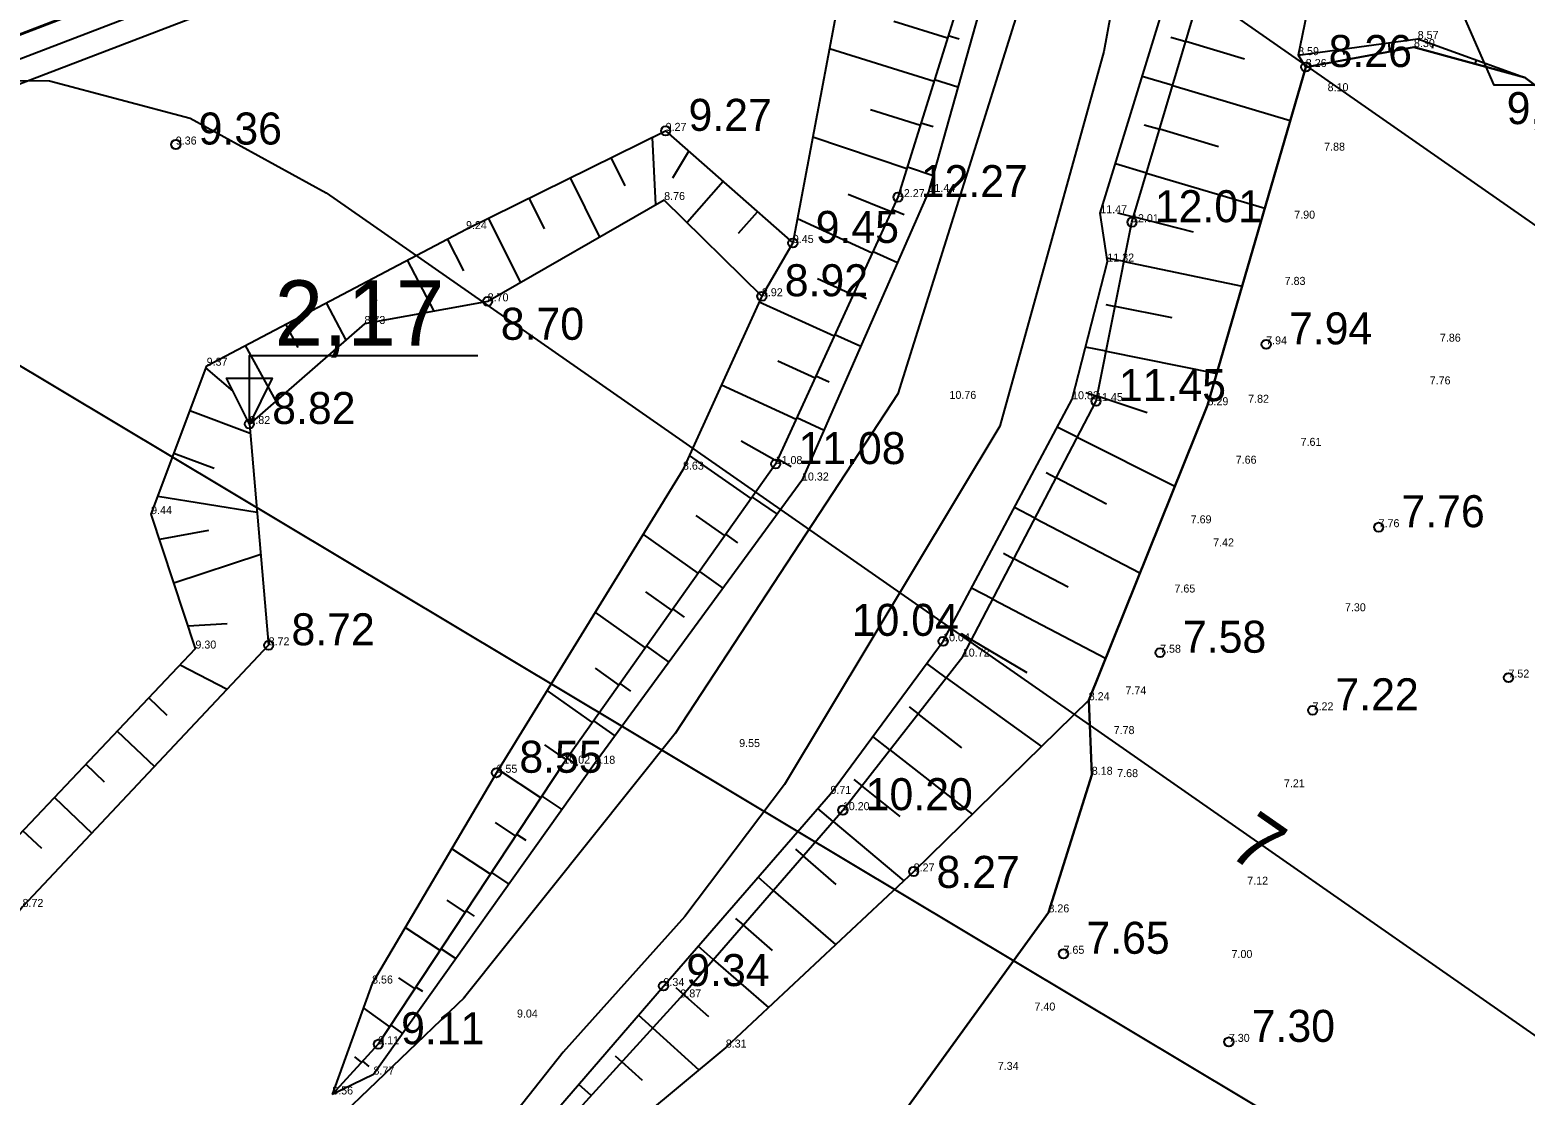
# Model space of a CAD drawing. Extents: x 433497 to 434382, y 6534486 to 6534993.
# Drawn here: x 433879.3 to 433944.7, y 6534844.8 to 6534891.4 of the extents above; entities that cross this region are included whole.
import ezdxf

# ---------------------------------------------------------------- set-up
doc = ezdxf.new("R2010")
doc.units = 0
for name, color, linetype in [('Default', 7, 'Continuous'), ('jääkpaksus', 7, 'Continuous'), ('kataster', 7, 'Continuous'), ('KORGUS-EH2000', 7, 'Continuous'), ('l__x00e4__bil__x00f5__iked', 7, 'Continuous'), ('Lamami horisontaal', 7, 'Continuous'), ('MOOTKORG-EH2000', 7, 'Continuous'), ('PIIR', 7, 'Continuous'), ('RELJEEF', 7, 'Continuous'), ('TEE', 7, 'Continuous'), ('TRUUP', 7, 'Continuous'), ('VEEKOGU', 7, 'Continuous')]:
    doc.layers.add(name, color=color, linetype=linetype)

msp = doc.modelspace()

# ---------------------------------------------------------------- linework, layer by layer
at = {"layer": 'Default'}
msp.add_lwpolyline([(433617.12, 6534791.025), (433632.75, 6534606.045), (434137.38, 6534796.515), (434127.69, 6534855.6), (433968.21, 6534911.925), (433942.38, 6534904.035), (433920.99, 6534907.275)], close=True, dxfattribs=at)
msp.add_lwpolyline([(433617.12, 6534791.025), (433632.75, 6534606.045), (434137.38, 6534796.515), (434127.69, 6534855.6), (433968.21, 6534911.925), (433942.38, 6534904.035), (433920.99, 6534907.275)], close=True, dxfattribs=at)
msp.add_lwpolyline([(433617.12, 6534791.025), (433632.75, 6534606.045), (434137.38, 6534796.515), (434127.69, 6534855.6), (433968.21, 6534911.925), (433942.38, 6534904.035), (433920.99, 6534907.275)], close=True, dxfattribs=at)
at = {"layer": 'jääkpaksus'}
msp.add_lwpolyline([(433888.875, 6534874.127), (433888.875, 6534877.127), (433898.875, 6534877.127)], dxfattribs=at)
msp.add_lwpolyline([(433888.875, 6534874.127), (433887.875, 6534876.127), (433889.875, 6534876.127)], close=True, dxfattribs=at)
at = {"layer": 'kataster'}
msp.add_lwpolyline([(433617.102, 6534791.002), (433632.769, 6534606.029), (434137.446, 6534796.469), (434127.827, 6534855.589), (433950.026, 6534918.39)], close=True, dxfattribs=at)
at = {"layer": 'KORGUS-EH2000'}
for centre in [(433935.088, 6534889.742), (433907.086, 6534886.949), (433885.657, 6534886.351), (433917.246, 6534884.05), (433927.486, 6534882.954), (433912.65, 6534882.047), (433899.301, 6534879.492), (433911.296, 6534879.715), (433933.355, 6534877.61), (433925.913, 6534875.128), (433888.875, 6534874.127), (433911.896, 6534872.374), (433938.274, 6534869.613), (433889.718, 6534864.448), (433919.223, 6534864.624), (433928.715, 6534864.123), (433943.954, 6534863.036), (433935.386, 6534861.605), (433899.687, 6534858.873), (433914.836, 6534857.237), (433917.937, 6534854.555), (433924.491, 6534850.955), (433906.99, 6534849.543), (433894.514, 6534847), (433931.723, 6534847.102)]:
    msp.add_circle(centre, 0.2, dxfattribs=at)
at = {"layer": 'l__x00e4__bil__x00f5__iked'}
msp.add_lwpolyline([(433837.129, 6534901.88), (433863.279, 6534885.992), (433986.579, 6534812.177), (434090.185, 6534779.904), (434120.969, 6534768.153)], dxfattribs=at)
at = {"layer": 'Lamami horisontaal'}
for points in [[(433901.435, 6534899.835), (433905.917, 6534900.93), (433913.287, 6534900.915), (433920.411, 6534899.023), (433927.288, 6534895.254), (433957.622, 6534874.107)], [(433873.126, 6534888.995), (433873.76, 6534889.15), (433880.129, 6534889.137), (433886.285, 6534887.502), (433892.228, 6534884.245), (433982.141, 6534821.565), (433982.939, 6534821.09), (433983.78, 6534820.746), (433984.663, 6534820.534), (433985.588, 6534820.453), (433989.375, 6534820.395), (433990.317, 6534820.349), (433991.249, 6534820.24), (433992.172, 6534820.067), (433993.085, 6534819.831), (434065.946, 6534798.347)]]:
    msp.add_lwpolyline(points, dxfattribs=at)
at = {"layer": 'PIIR'}
msp.add_lwpolyline([(433632.732, 6534605.959), (434137.353, 6534796.454), (434127.754, 6534855.539), (433968.208, 6534911.976), (433942.39, 6534904.031), (433921.04, 6534907.341), (433617.174, 6534790.992), (433632.732, 6534605.959)], dxfattribs=at)
for points in [[(433618.234, 6534790.327), (433921.149, 6534906.313), (433942.464, 6534903.008), (433968.187, 6534910.923), (434126.862, 6534854.794), (434136.235, 6534797.101), (433633.617, 6534607.362)], [(433619.24, 6534789.695), (433634.52, 6534608.851), (434135.141, 6534797.808), (434125.908, 6534854.108), (433968.165, 6534909.82), (433942.53, 6534901.99), (433921.212, 6534905.219)], [(433619.24, 6534789.695), (433634.52, 6534608.851), (434135.141, 6534797.808), (434125.908, 6534854.108), (433968.165, 6534909.82), (433942.53, 6534901.99), (433921.212, 6534905.219)]]:
    msp.add_lwpolyline(points, close=True, dxfattribs=at)
at = {"layer": 'RELJEEF'}
for p, q in [((433917.074, 6534891.754), (433919.42, 6534891.023)), ((433919.93, 6534890.956), (433919.447, 6534891.107)), ((433929.18, 6534891.049), (433929.84, 6534890.852)), ((433932.403, 6534890.088), (433929.84, 6534890.852)), ((433938.717, 6534890.797), (433938.736, 6534890.413)), ((433918.825, 6534889.114), (433914.25, 6534890.54)), ((433936.767, 6534890.293), (433936.735, 6534890.529)), ((433940.631, 6534890.562), (433940.663, 6534890.725)), ((433942.544, 6534890.047), (433942.485, 6534889.882)), ((433918.851, 6534889.198), (433919.874, 6534888.879)), ((433929.269, 6534888.936), (433927.934, 6534889.333)), ((433929.269, 6534888.936), (433934.409, 6534887.404)), ((433944.423, 6534889.36), (433944.426, 6534889.37)), ((433944.672, 6534889.281), (433944.672, 6534889.281)), ((433916.053, 6534887.883), (433918.23, 6534887.204)), ((433918.795, 6534887.12), (433918.256, 6534887.288)), ((433928.023, 6534887.22), (433928.698, 6534887.019)), ((433931.274, 6534886.251), (433928.698, 6534887.019)), ((433906.503, 6534886.662), (433906.643, 6534883.707)), ((433917.634, 6534885.295), (433913.522, 6534886.678)), ((433905.319, 6534884.538), (433904.709, 6534885.779)), ((433907.402, 6534884.899), (433908.099, 6534886.056)), ((433902.914, 6534884.896), (433904.192, 6534882.3)), ((433917.66, 6534885.379), (433918.788, 6534885.003)), ((433928.126, 6534885.102), (433926.762, 6534885.509)), ((433928.126, 6534885.102), (433933.293, 6534883.563)), ((433909.6, 6534884.734), (433908.02, 6534882.941)), ((433901.787, 6534882.657), (433901.12, 6534884.013)), ((433915.077, 6534884.186), (433916.956, 6534883.417)), ((433899.325, 6534883.13), (433900.733, 6534880.314)), ((433910.274, 6534882.474), (433911.101, 6534883.412)), ((433916.123, 6534881.599), (433912.848, 6534883.1)), ((433917.523, 6534883.282), (433916.993, 6534883.497)), ((433926.857, 6534883.364), (433927.555, 6534883.186)), ((433930.175, 6534882.518), (433927.555, 6534883.186)), ((433898.264, 6534880.829), (433897.542, 6534882.224)), ((433916.16, 6534881.679), (433917.23, 6534881.189)), ((433895.773, 6534881.292), (433896.948, 6534879.06)), ((433927.14, 6534881.23), (433926.385, 6534881.386)), ((433927.14, 6534881.23), (433932.305, 6534880.162)), ((433894.445, 6534879.521), (433894.003, 6534880.36)), ((433913.728, 6534880.497), (433915.29, 6534879.781)), ((433915.877, 6534879.609), (433915.327, 6534879.861)), ((433892.234, 6534879.428), (433893.094, 6534877.793)), ((433914.457, 6534877.963), (433911.181, 6534879.463)), ((433926.346, 6534879.35), (433926.745, 6534879.269)), ((433929.249, 6534878.766), (433926.745, 6534879.269)), ((433891.004, 6534877.471), (433890.464, 6534878.496)), ((433914.493, 6534878.043), (433915.624, 6534877.525)), ((433888.694, 6534877.564), (433890.027, 6534875.128)), ((433926.351, 6534877.309), (433925.45, 6534877.49)), ((433926.351, 6534877.309), (433931.193, 6534876.336)), ((433888.169, 6534875.569), (433886.975, 6534876.588)), ((433911.988, 6534876.894), (433913.624, 6534876.144)), ((433912.79, 6534874.326), (433909.524, 6534875.823)), ((433914.24, 6534875.959), (433913.66, 6534876.225)), ((433925.471, 6534875.511), (433925.957, 6534875.348)), ((433928.157, 6534874.61), (433925.957, 6534875.348)), ((433886.274, 6534874.715), (433888.91, 6534873.728)), ((433912.827, 6534874.406), (433914.017, 6534873.861)), ((433925.092, 6534873.554), (433924.217, 6534873.993)), ((433910.391, 6534873.397), (433911.957, 6534872.508)), ((433925.092, 6534873.554), (433929.365, 6534871.41)), ((433887.337, 6534872.181), (433885.572, 6534872.842)), ((433910.825, 6534870.863), (433908.125, 6534872.749)), ((433912.582, 6534872.258), (433911.994, 6534872.588)), ((433923.725, 6534872.011), (433924.167, 6534871.78)), ((433926.376, 6534870.628), (433924.167, 6534871.78)), ((433884.871, 6534870.969), (433889.211, 6534870.267)), ((433910.876, 6534870.934), (433911.967, 6534870.179)), ((433908.412, 6534870.121), (433909.668, 6534869.231)), ((433923.242, 6534870.007), (433922.342, 6534870.476)), ((433923.242, 6534870.007), (433927.835, 6534867.611)), ((433887.095, 6534869.468), (433884.942, 6534869.08)), ((433908.512, 6534867.599), (433906.105, 6534869.305)), ((433910.248, 6534868.928), (433909.719, 6534869.303)), ((433885.568, 6534867.181), (433889.371, 6534868.434)), ((433921.859, 6534868.473), (433922.317, 6534868.234)), ((433924.701, 6534866.991), (433922.317, 6534868.234)), ((433908.563, 6534867.671), (433909.594, 6534866.94)), ((433906.205, 6534866.783), (433907.355, 6534865.967)), ((433921.392, 6534866.461), (433920.461, 6534866.946)), ((433907.909, 6534865.683), (433907.406, 6534866.039)), ((433921.392, 6534866.461), (433926.333, 6534863.883)), ((433887.911, 6534865.38), (433886.194, 6534865.281)), ((433906.199, 6534864.336), (433904.005, 6534865.891)), ((433920.007, 6534864.96), (433920.467, 6534864.687)), ((433922.905, 6534863.244), (433920.467, 6534864.687)), ((433906.25, 6534864.408), (433907.229, 6534863.713)), ((433885.848, 6534863.599), (433887.908, 6534862.524)), ((433903.998, 6534863.444), (433905.042, 6534862.704)), ((433919.362, 6534863.03), (433918.504, 6534863.65)), ((433905.57, 6534862.438), (433905.093, 6534862.776)), ((433919.362, 6534863.03), (433923.525, 6534860.023)), ((433885.287, 6534861.376), (433884.472, 6534862.148)), ((433903.885, 6534861.072), (433901.904, 6534862.477)), ((433917.735, 6534861.763), (433918.131, 6534861.454)), ((433920.037, 6534859.964), (433918.131, 6534861.454)), ((433883.097, 6534860.696), (433884.731, 6534859.147)), ((433903.936, 6534861.144), (433904.864, 6534860.487)), ((433901.782, 6534860.09), (433902.729, 6534859.441)), ((433916.899, 6534859.878), (433916.151, 6534860.463)), ((433903.238, 6534859.197), (433902.78, 6534859.513)), ((433916.899, 6534859.878), (433920.501, 6534857.064)), ((433882.541, 6534858.467), (433881.721, 6534859.244)), ((433901.622, 6534857.775), (433899.767, 6534859.003)), ((433915.317, 6534858.581), (433915.668, 6534858.302)), ((433917.351, 6534856.965), (433915.668, 6534858.302)), ((433880.345, 6534857.792), (433881.991, 6534856.233)), ((433901.67, 6534857.849), (433902.548, 6534857.267)), ((433914.411, 6534856.747), (433913.739, 6534857.31)), ((433879.795, 6534855.558), (433878.97, 6534856.34)), ((433899.633, 6534856.691), (433900.521, 6534856.106)), ((433900.98, 6534855.908), (433900.569, 6534856.179)), ((433914.411, 6534856.747), (433917.508, 6534854.153)), ((433899.419, 6534854.436), (433897.727, 6534855.553)), ((433912.769, 6534855.524), (433913.1, 6534855.236)), ((433914.545, 6534853.983), (433913.1, 6534855.236)), ((433899.468, 6534854.51), (433900.231, 6534854.007)), ((433911.79, 6534853.726), (433911.126, 6534854.302)), ((433911.79, 6534853.726), (433914.522, 6534851.355)), ((433897.513, 6534853.298), (433898.318, 6534852.767)), ((433898.719, 6534852.608), (433898.367, 6534852.84)), ((433910.146, 6534852.504), (433910.479, 6534852.215)), ((433911.767, 6534851.098), (433910.479, 6534852.215)), ((433897.217, 6534851.097), (433895.691, 6534852.104)), ((433897.265, 6534851.171), (433897.911, 6534850.745)), ((433909.168, 6534850.705), (433908.502, 6534851.283)), ((433909.168, 6534850.705), (433911.587, 6534848.606)), ((433895.394, 6534849.904), (433896.115, 6534849.428)), ((433896.458, 6534849.307), (433896.164, 6534849.501)), ((433907.527, 6534849.487), (433907.857, 6534849.194)), ((433908.977, 6534848.202), (433907.857, 6534849.194)), ((433895.014, 6534847.758), (433893.862, 6534848.592)), ((433906.515, 6534847.711), (433905.895, 6534848.274)), ((433895.063, 6534847.832), (433895.578, 6534847.462)), ((433906.515, 6534847.711), (433908.539, 6534845.874)), ((433893.48, 6534846.448), (433893.777, 6534846.195)), ((433904.879, 6534846.496), (433905.169, 6534846.232)), ((433894.113, 6534846.026), (433893.836, 6534846.26)), ((433906.076, 6534845.407), (433905.169, 6534846.232)), ((433903.823, 6534844.753), (433903.282, 6534845.245)), ((433892.501, 6534844.802), (433892.501, 6534844.802)), ((433892.501, 6534844.802), (433892.501, 6534844.802))]:
    msp.add_line(p, q, dxfattribs=at)
for points in [[(433896.085, 6534836.246), (433907.73, 6534849.047), (433914.836, 6534857.237), (433920.085, 6534863.955), (433925.913, 6534875.128), (433927.486, 6534882.954), (433931.452, 6534896.261), (433930.509, 6534901.55), (433930.322, 6534906.766), (433932.632, 6534912.431), (433936.113, 6534913.569), (433948.309, 6534917.667)], [(433895.887, 6534836.671), (433906.99, 6534849.543), (433914.294, 6534857.948), (433919.223, 6534864.624), (433924.866, 6534875.211), (433926.408, 6534881.232), (433926.099, 6534883.348), (433929.589, 6534894.729), (433930.371, 6534898.093), (433929.278, 6534901.297), (433929.803, 6534907.342), (433932.713, 6534913.57), (433935.494, 6534915.253), (433941.232, 6534917.143)], [(433953.287, 6534916.572), (433941.75, 6534912.389), (433938.749, 6534910.421), (433935.41, 6534908.231), (433934.834, 6534906.421), (433935.357, 6534904.952), (433937.075, 6534905.296), (433935.31, 6534904.512), (433934.725, 6534902.808), (433934.885, 6534901.473), (433935.534, 6534899.657), (433935.756, 6534895.142), (433934.753, 6534890.261), (433935.088, 6534889.742), (433930.79, 6534874.949), (433925.594, 6534862.047), (433917.937, 6534854.555), (433909.717, 6534846.854), (433896.607, 6534835.953)], [(433922.121, 6534910.322), (433922.204, 6534910.54), (433922.59, 6534912.061), (433924.695, 6534910.843), (433924.54, 6534902.576), (433923.354, 6534897.907), (433921.669, 6534895.285), (433918.585, 6534884.278), (433913.05, 6534871.656), (433903.969, 6534859.265), (433894.305, 6534845.672), (433892.501, 6534844.802)], [(433923.615, 6534910.205), (433923.798, 6534901.905), (433922.62, 6534898.344), (433920.827, 6534895.534), (433917.246, 6534884.05), (433911.896, 6534872.374), (433902.608, 6534859.27), (433894.514, 6534847), (433892.501, 6534844.802)], [(433907.052, 6534907.24), (433916.008, 6534904.516), (433917.858, 6534906.468), (433920.952, 6534907.058), (433921.355, 6534906.578), (433918.811, 6534901.575), (433917.104, 6534899.283), (433914.485, 6534891.79), (433912.65, 6534882.047), (433911.296, 6534879.715), (433907.843, 6534872.13), (433899.687, 6534858.873), (433894.244, 6534849.654), (433892.501, 6534844.802)], [(433934.753, 6534890.261), (433939.985, 6534890.969), (433944.672, 6534889.281)], [(433935.088, 6534889.742), (433939.821, 6534890.613), (433944.672, 6534889.281)], [(433841.869, 6534810.001), (433847.43, 6534813.32), (433854.131, 6534816.888), (433858.193, 6534830.595), (433861.302, 6534838.643), (433876.465, 6534853.696), (433886.516, 6534864.305), (433884.578, 6534870.186), (433887.008, 6534876.676), (433898.353, 6534882.651), (433907.086, 6534886.949), (433912.65, 6534882.047)], [(433911.296, 6534879.715), (433907.021, 6534883.924), (433899.301, 6534879.492), (433893.911, 6534878.503), (433888.875, 6534874.127), (433889.718, 6534864.448), (433878.953, 6534853.004), (433869.246, 6534840.579), (433864.604, 6534835.364), (433860.654, 6534826.36), (433857.473, 6534817.518), (433856.122, 6534814.892), (433847.64, 6534811.737), (433841.869, 6534810.001)]]:
    msp.add_lwpolyline(points, dxfattribs=at)
at = {"layer": 'TEE'}
for points in [[(433861.438, 6534942.159), (433869.211, 6534941.983), (433884.56, 6534941.789), (433912.385, 6534941.438), (433914.504, 6534939.939), (433923.131, 6534931.509), (433926.468, 6534922.294), (433926.566, 6534912.494), (433924.107, 6534897.344), (433917.239, 6534875.453), (433907.496, 6534860.59), (433898.243, 6534848.994), (433898.296, 6534849.051), (433891.969, 6534842.99)], [(433946.971, 6534921.598), (433938.961, 6534918.789), (433932.862, 6534915.346), (433929.862, 6534910.084), (433927.993, 6534899.902), (433926.253, 6534890.427), (433921.703, 6534874.038), (433912.286, 6534858.358), (433907.932, 6534852.587), (433902.598, 6534846.653), (433894.713, 6534836.682), (433880.242, 6534822.442), (433871.952, 6534814.761), (433862.656, 6534809.713), (433848.041, 6534804.286)]]:
    msp.add_lwpolyline(points, dxfattribs=at)
at = {"layer": 'TRUUP'}
msp.add_lwpolyline([(433952.849, 6534888.951), (433943.324, 6534888.951), (433935.611, 6534906.595)], dxfattribs=at)
at = {"layer": 'VEEKOGU'}
for points in [[(433905.134, 6534762.547), (433916.484, 6534767.586), (433919.938, 6534769.068), (433922.013, 6534770.671), (433923.404, 6534772.606), (433925.761, 6534778.847), (433926.29, 6534784.28), (433925.378, 6534788.845), (433922.624, 6534792.819), (433910.743, 6534798.994), (433899.798, 6534804.634), (433898.901, 6534806.241), (433900.552, 6534813.199), (433903.795, 6534819.986), (433911.474, 6534835.66), (433917.335, 6534843.781), (433923.831, 6534852.766), (433925.728, 6534858.785), (433925.594, 6534862.047), (433930.79, 6534874.949), (433935.088, 6534889.742), (433939.821, 6534890.613), (433944.672, 6534889.281), (433947.125, 6534887.427)], [(433950.327, 6534886.209), (433947.125, 6534887.427), (433944.672, 6534889.281), (433939.821, 6534890.613), (433935.088, 6534889.742), (433930.79, 6534874.949), (433925.594, 6534862.047), (433925.728, 6534858.785), (433923.831, 6534852.766), (433917.335, 6534843.781), (433911.474, 6534835.66), (433903.795, 6534819.986), (433900.681, 6534813.47)]]:
    msp.add_lwpolyline(points, dxfattribs=at)

# ---------------------------------------------------------------- texts
at = {"layer": 'jääkpaksus'}
msp.add_text('2,17', height=2.85, rotation=360, dxfattribs=at).set_placement((433889.985, 6534877.559))
at = {"layer": 'KORGUS-EH2000'}
for s, p in [('8.26', (433936.088, 6534889.742)), ('9.27', (433908.086, 6534886.949)), ('9.36', (433886.657, 6534886.351)), ('12.27', (433918.246, 6534884.05)), ('12.01', (433928.486, 6534882.954)), ('9.45', (433913.65, 6534882.047)), ('8.92', (433912.296, 6534879.715)), ('8.70', (433899.875, 6534877.81)), ('7.94', (433934.355, 6534877.61)), ('11.45', (433926.913, 6534875.128)), ('8.82', (433889.875, 6534874.127)), ('11.08', (433912.896, 6534872.374)), ('7.76', (433939.274, 6534869.613)), ('10.04', (433915.226, 6534864.861)), ('8.72', (433890.718, 6534864.448)), ('7.58', (433929.715, 6534864.123)), ('7.22', (433936.386, 6534861.605)), ('8.55', (433900.687, 6534858.873)), ('10.20', (433915.836, 6534857.237)), ('8.27', (433918.937, 6534853.837)), ('7.65', (433925.491, 6534850.955)), ('9.34', (433907.99, 6534849.543)), ('9.11', (433895.514, 6534847)), ('7.30', (433932.723, 6534847.102))]:
    msp.add_text(s, height=1.4, dxfattribs=at).set_placement(p)
at = {"layer": 'Lamami horisontaal'}
msp.add_text('7', height=2.4, rotation=325.11916, dxfattribs=at).set_placement((433931.602, 6534855.334))
at = {"layer": 'MOOTKORG-EH2000'}
for s, p in [('8.30', (433939.821, 6534890.613)), ('8.57', (433939.985, 6534890.969)), ('8.59', (433934.753, 6534890.261)), ('8.26', (433935.088, 6534889.742)), ('8.10', (433936.044, 6534888.685)), ('9.27', (433907.086, 6534886.949)), ('9.36', (433885.657, 6534886.351)), ('7.88', (433935.892, 6534886.084)), ('8.76', (433907.021, 6534883.924)), ('12.27', (433917.246, 6534884.05)), ('11.44', (433918.585, 6534884.278)), ('11.47', (433926.099, 6534883.348)), ('9.24', (433898.353, 6534882.651)), ('12.01', (433927.486, 6534882.954)), ('7.90', (433934.584, 6534883.109)), ('9.45', (433912.65, 6534882.047)), ('11.32', (433926.408, 6534881.232)), ('7.83', (433934.164, 6534880.212)), ('8.70', (433899.301, 6534879.492)), ('8.92', (433911.296, 6534879.715)), ('8.73', (433893.911, 6534878.503)), ('7.94', (433933.355, 6534877.61)), ('7.86', (433940.956, 6534877.73)), ('9.37', (433887.008, 6534876.676)), ('7.76', (433940.509, 6534875.861)), ('10.76', (433919.501, 6534875.225)), ('10.82', (433924.866, 6534875.211)), ('11.45', (433925.913, 6534875.128)), ('8.29', (433930.79, 6534874.949)), ('7.82', (433932.567, 6534875.056)), ('8.82', (433888.875, 6534874.127)), ('7.61', (433934.862, 6534873.172)), ('8.63', (433907.843, 6534872.13)), ('11.08', (433911.896, 6534872.374)), ('7.66', (433932.023, 6534872.391)), ('10.32', (433913.05, 6534871.656)), ('9.44', (433884.578, 6534870.186)), ('7.69', (433930.053, 6534869.783)), ('7.76', (433938.274, 6534869.613)), ('7.42', (433931.037, 6534868.773)), ('7.65', (433929.344, 6534866.757)), ('7.30', (433936.802, 6534865.936)), ('9.30', (433886.516, 6534864.305)), ('8.72', (433889.718, 6534864.448)), ('10.04', (433919.223, 6534864.624)), ('10.72', (433920.085, 6534863.955)), ('7.58', (433928.715, 6534864.123)), ('7.52', (433943.954, 6534863.036)), ('7.74', (433927.201, 6534862.304)), ('8.24', (433925.594, 6534862.047)), ('7.22', (433935.386, 6534861.605)), ('7.78', (433926.685, 6534860.564)), ('9.55', (433910.302, 6534859.997)), ('10.02', (433902.608, 6534859.27)), ('9.18', (433903.969, 6534859.265)), ('8.55', (433899.687, 6534858.873)), ('8.18', (433925.728, 6534858.785)), ('7.68', (433926.84, 6534858.682)), ('9.71', (433914.294, 6534857.948)), ('7.21', (433934.132, 6534858.236)), ('10.20', (433914.836, 6534857.237)), ('8.27', (433917.937, 6534854.555)), ('7.12', (433932.528, 6534853.979)), ('8.72', (433878.953, 6534853.004)), ('8.26', (433923.831, 6534852.766)), ('7.65', (433924.491, 6534850.955)), ('7.00', (433931.84, 6534850.772)), ('8.56', (433894.244, 6534849.654)), ('9.34', (433906.99, 6534849.543)), ('9.87', (433907.73, 6534849.047)), ('9.04', (433900.582, 6534848.167)), ('7.40', (433923.22, 6534848.472)), ('9.11', (433894.514, 6534847)), ('8.31', (433909.717, 6534846.854)), ('7.30', (433931.723, 6534847.102)), ('8.77', (433894.305, 6534845.672)), ('7.34', (433921.615, 6534845.877)), ('8.56', (433892.501, 6534844.802))]:
    msp.add_text(s, height=0.35, dxfattribs=at).set_placement(p)
at = {"layer": 'TRUUP'}
msp.add_text('9,08-8,92', height=1.4, dxfattribs=at).set_placement((433943.878, 6534887.244))

doc.saveas('drawing.dxf')
